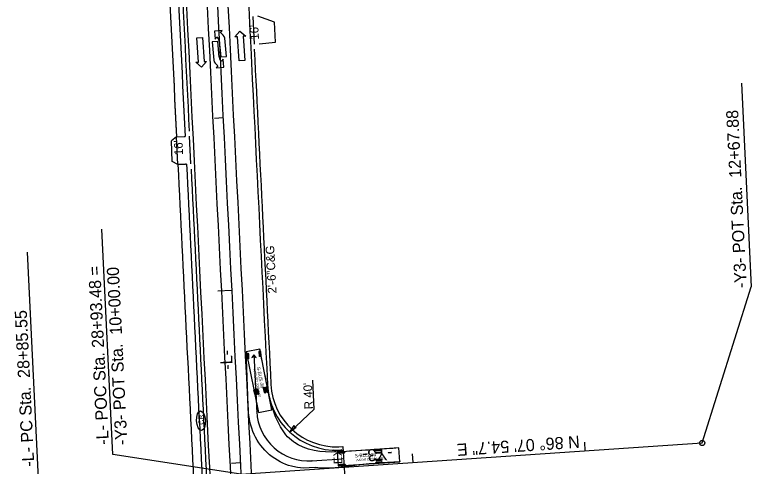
# Model space of a CAD drawing. Extents: x 2367848 to 2369479, y 800728 to 808616.
# Drawn here: x 2368732.6 to 2369159.2, y 803226.7 to 803488.2 of the extents above; entities that cross this region are included whole.
import ezdxf

# ---------------------------------------------------------------- set-up
doc = ezdxf.new("R2010")
doc.units = 0
for name, color, linetype in [('Prop AutoTurn Projected Path', 7, 'Continuous'), ('Prop AutoTurn Simulation', 7, 'Continuous'), ('Prop Conc 2ft 6in Curb and Gutter', 7, 'Continuous'), ('Prop Conc 4in Sidewalk', 7, 'Continuous'), ('Prop Conc Drive Radius Type', 7, 'Continuous'), ('Prop Conc Driveway', 7, 'Continuous'), ('Prop Dimension', 7, 'Continuous'), ('Prop EOT', 7, 'Continuous'), ('Prop Horizontal Alignment', 7, 'Continuous'), ('Prop Horizontal Alignment Direction Label', 7, 'Continuous'), ('Prop Horizontal Alignment Station Label', 7, 'Continuous'), ('Prop Horizontal Alignment Tick Large', 7, 'Continuous'), ('Prop Horizontal Alignment Tick Small', 7, 'Continuous'), ('Prop Lane Arrow CELL', 7, 'Continuous'), ('Prop Lane Lines', 7, 'Continuous'), ('Prop Shade Light', 7, 'Continuous'), ('Prop Terminator CELL', 7, 'Continuous'), ('Prop WCC CELL', 7, 'Continuous'), ('Prop WCR CELL', 7, 'Continuous')]:
    doc.layers.add(name, color=color, linetype=linetype)

# ---------------------------------------------------------------- blocks, each defined once
blk = doc.blocks.new('CR')
at = {"layer": 'Prop WCC CELL'}
blk.add_ellipse((0.02, -0.02), major_axis=(5.61, 0), ratio=0.462467, dxfattribs=at)
blk.add_text('CR', height=3, dxfattribs=at).set_placement((-2.34, -1.5))

msp = doc.modelspace()

# ---------------------------------------------------------------- linework, layer by layer
at = {"layer": 'Prop AutoTurn Projected Path'}
msp.add_line((2368904.73, 803229.94), (2368922.15, 803231.12), dxfattribs=at)
for centre, radius, start, end in [((2677047.33, 818679.94), 308560.21, 182.8586672, 182.8647861), ((2368902.7, 803259.87), 30, 182.8648, 273.8681)]:
    msp.add_arc(centre, radius, start, end, dxfattribs=at)
at = {"layer": 'Prop AutoTurn Simulation'}
for p, q in [((2368874.53, 803294.52), (2368866.68, 803292.95)), ((2368866.68, 803292.95), (2368873.73, 803257.85)), ((2368866.68, 803292.95), (2368866.68, 803292.95)), ((2368867.28, 803292.29), (2368867.45, 803288.97)), ((2368867.49, 803292.3), (2368867.66, 803288.98)), ((2368867.69, 803292.32), (2368867.87, 803288.99)), ((2368874.33, 803293.58), (2368874.49, 803290.25)), ((2368881.57, 803259.42), (2368874.53, 803294.52)), ((2368874.54, 803293.59), (2368874.69, 803290.26)), ((2368874.75, 803293.6), (2368874.9, 803290.27)), ((2368871.24, 803271.29), (2368871.9, 803268.02)), ((2368871.44, 803271.33), (2368872.1, 803268.06)), ((2368871.65, 803271.37), (2368872.3, 803268.1)), ((2368872.71, 803271.59), (2368873.37, 803268.32)), ((2368872.92, 803271.63), (2368873.57, 803268.36)), ((2368873.12, 803271.67), (2368873.78, 803268.4)), ((2368876.8, 803272.4), (2368877.45, 803269.14)), ((2368877, 803272.45), (2368877.66, 803269.18)), ((2368877.2, 803272.49), (2368877.86, 803269.22)), ((2368878.27, 803272.7), (2368878.92, 803269.43)), ((2368878.47, 803272.74), (2368879.13, 803269.47)), ((2368878.68, 803272.78), (2368879.33, 803269.51)), ((2368873.73, 803257.85), (2368881.57, 803259.42)), ((2368955.11, 803237.36), (2368919.39, 803234.94)), ((2368955.65, 803229.38), (2368955.11, 803237.36)), ((2368919.39, 803234.94), (2368919.93, 803226.96)), ((2368920.23, 803234.79), (2368923.56, 803235.02)), ((2368920.25, 803234.58), (2368923.57, 803234.81)), ((2368920.26, 803234.38), (2368923.59, 803234.6)), ((2368941.49, 803236.23), (2368944.81, 803236.45)), ((2368941.5, 803236.02), (2368944.83, 803236.24)), ((2368941.51, 803235.81), (2368944.84, 803236.04)), ((2368941.59, 803234.73), (2368944.91, 803234.96)), ((2368941.6, 803234.52), (2368944.93, 803234.75)), ((2368941.62, 803234.32), (2368944.94, 803234.54)), ((2368919.93, 803226.96), (2368955.65, 803229.38)), ((2368941.87, 803230.57), (2368945.19, 803230.8)), ((2368941.88, 803230.37), (2368945.21, 803230.59)), ((2368941.9, 803230.16), (2368945.22, 803230.38)), ((2368941.97, 803229.08), (2368945.3, 803229.3)), ((2368941.98, 803228.87), (2368945.31, 803229.09)), ((2368942, 803228.66), (2368945.32, 803228.89)), ((2368919.93, 803226.96), (2368919.93, 803226.96)), ((2368920.72, 803227.64), (2368924.04, 803227.87)), ((2368920.73, 803227.43), (2368924.06, 803227.66)), ((2368920.75, 803227.22), (2368924.07, 803227.45))]:
    msp.add_line(p, q, dxfattribs=at)
for points in [[(2368893.62, 803226.58), (2368892.94, 803226.75), (2368891.24, 803227.26), (2368889.56, 803227.86), (2368887.91, 803228.56), (2368886.28, 803229.36), (2368884.7, 803230.25), (2368883.16, 803231.22), (2368881.66, 803232.29), (2368880.22, 803233.44), (2368878.84, 803234.67), (2368877.53, 803235.97), (2368876.28, 803237.36), (2368875.11, 803238.81), (2368874.01, 803240.32), (2368873, 803241.9), (2368872.07, 803243.54), (2368871.23, 803245.22), (2368870.48, 803246.96), (2368869.83, 803248.73), (2368869.28, 803250.54), (2368868.82, 803252.38), (2368868.46, 803254.24), (2368868.21, 803256.13), (2368868.06, 803258.03), (2368867.95, 803259.92), (2368867.85, 803261.81), (2368867.76, 803263.68), (2368867.67, 803265.53), (2368867.59, 803267.38), (2368867.52, 803269.21), (2368867.45, 803271.04), (2368867.39, 803272.85), (2368867.32, 803274.65), (2368867.26, 803276.44), (2368867.2, 803278.23), (2368867.14, 803280.01), (2368867.08, 803281.77), (2368867.02, 803283.54), (2368866.96, 803285.29), (2368866.9, 803287.04), (2368866.83, 803288.78), (2368866.77, 803290.52), (2368866.71, 803292.26), (2368866.68, 803292.95)], [(2368894.57, 803240.55), (2368894.07, 803240.91), (2368892.85, 803241.83), (2368891.71, 803242.82), (2368890.65, 803243.85), (2368889.68, 803244.92), (2368888.78, 803246.04), (2368887.96, 803247.17), (2368887.21, 803248.33), (2368886.51, 803249.5), (2368885.86, 803250.67), (2368885.26, 803251.84), (2368884.7, 803253.02), (2368884.18, 803254.19), (2368883.7, 803255.36), (2368883.24, 803256.52), (2368882.82, 803257.68), (2368882.42, 803258.83), (2368882.04, 803259.97), (2368881.69, 803261.11), (2368881.35, 803262.24), (2368881.04, 803263.36), (2368880.74, 803264.48), (2368880.46, 803265.59), (2368880.19, 803266.7), (2368879.92, 803267.84), (2368879.65, 803269.04), (2368879.39, 803270.29), (2368879.13, 803271.59), (2368878.86, 803272.92), (2368878.59, 803274.29), (2368878.3, 803275.69), (2368878.02, 803277.11), (2368877.73, 803278.56), (2368877.43, 803280.03), (2368877.13, 803281.52), (2368876.83, 803283.02), (2368876.53, 803284.54), (2368876.22, 803286.08), (2368875.91, 803287.62), (2368875.6, 803289.18), (2368875.28, 803290.74), (2368874.97, 803292.31), (2368874.65, 803293.89), (2368874.53, 803294.52)], [(2368955.11, 803237.36), (2368951.54, 803237.12), (2368947.96, 803236.87), (2368944.39, 803236.63), (2368940.82, 803236.39), (2368937.25, 803236.15), (2368933.68, 803235.91), (2368930.1, 803235.67), (2368926.53, 803235.43), (2368922.96, 803235.19), (2368919.39, 803235.01), (2368919.39, 803235.01), (2368919.39, 803235.01), (2368916.03, 803234.95), (2368912.67, 803235.04), (2368909.33, 803235.34), (2368906.01, 803235.88), (2368902.76, 803236.7), (2368899.63, 803237.82), (2368896.72, 803239.23), (2368894.57, 803240.55)], [(2368955.65, 803229.38), (2368952.08, 803229.13), (2368948.5, 803228.89), (2368944.93, 803228.65), (2368941.36, 803228.41), (2368937.79, 803228.17), (2368934.22, 803227.82), (2368930.66, 803227.34), (2368927.08, 803226.86), (2368923.48, 803226.35), (2368919.85, 803225.94), (2368919.85, 803225.94), (2368916.43, 803225.7), (2368913.03, 803225.62), (2368909.69, 803225.71), (2368906.52, 803226.05), (2368903.17, 803225.83), (2368899.8, 803225.73), (2368896.37, 803226.04), (2368893.62, 803226.58)]]:
    msp.add_lwpolyline(points, dxfattribs=at)
for points in [[(2368867.23, 803292.29), (2368867.75, 803292.32), (2368867.93, 803291.86), (2368868.05, 803289.46), (2368867.92, 803288.99), (2368867.4, 803288.96), (2368867.22, 803289.42), (2368867.09, 803291.82)], [(2368874.28, 803293.58), (2368874.8, 803293.6), (2368874.98, 803293.15), (2368875.09, 803290.75), (2368874.95, 803290.28), (2368874.43, 803290.25), (2368874.26, 803290.71), (2368874.14, 803293.11)], [(2368871.1, 803291.29), (2368869.96, 803289.64), (2368871.15, 803290.29), (2368872.39, 803289.76)], [(2368871.19, 803271.28), (2368871.7, 803271.38), (2368871.95, 803270.96), (2368872.42, 803268.6), (2368872.36, 803268.11), (2368871.85, 803268.01), (2368871.6, 803268.44), (2368871.13, 803270.79)], [(2368872.66, 803271.57), (2368873.17, 803271.68), (2368873.42, 803271.25), (2368873.89, 803268.9), (2368873.83, 803268.41), (2368873.32, 803268.31), (2368873.07, 803268.73), (2368872.6, 803271.09)], [(2368876.75, 803272.39), (2368877.26, 803272.5), (2368877.5, 803272.07), (2368877.97, 803269.72), (2368877.91, 803269.23), (2368877.4, 803269.13), (2368877.16, 803269.55), (2368876.68, 803271.91)], [(2368878.22, 803272.69), (2368878.73, 803272.79), (2368878.97, 803272.37), (2368879.44, 803270.01), (2368879.38, 803269.52), (2368878.87, 803269.42), (2368878.63, 803269.85), (2368878.15, 803272.2)], [(2368941.52, 803235.76), (2368941.48, 803236.28), (2368941.94, 803236.47), (2368944.33, 803236.63), (2368944.81, 803236.5), (2368944.84, 803235.99), (2368944.39, 803235.8), (2368941.99, 803235.64)], [(2368920.27, 803234.32), (2368920.23, 803234.84), (2368920.69, 803235.03), (2368923.08, 803235.19), (2368923.56, 803235.07), (2368923.59, 803234.55), (2368923.14, 803234.36), (2368920.74, 803234.2)], [(2368941.62, 803234.26), (2368941.58, 803234.78), (2368942.04, 803234.97), (2368944.43, 803235.13), (2368944.91, 803235.01), (2368944.94, 803234.49), (2368944.49, 803234.3), (2368942.1, 803234.14)], [(2368920.75, 803227.17), (2368920.71, 803227.69), (2368921.17, 803227.88), (2368923.56, 803228.04), (2368924.04, 803227.92), (2368924.08, 803227.4), (2368923.62, 803227.21), (2368921.23, 803227.05)], [(2368941.9, 803230.11), (2368941.87, 803230.63), (2368942.32, 803230.81), (2368944.71, 803230.98), (2368945.19, 803230.85), (2368945.23, 803230.33), (2368944.77, 803230.14), (2368942.38, 803229.98)], [(2368942, 803228.61), (2368941.97, 803229.13), (2368942.42, 803229.32), (2368944.82, 803229.48), (2368945.29, 803229.35), (2368945.33, 803228.84), (2368944.87, 803228.65), (2368942.48, 803228.49)]]:
    msp.add_lwpolyline(points, close=True, dxfattribs=at)
for centre in [(2368866.68, 803292.95), (2368874.53, 803294.52), (2368871.1, 803291.29), (2368872.74, 803258.37), (2368872.74, 803258.37), (2368894.57, 803240.55), (2368894.57, 803240.55), (2368955.11, 803237.36), (2368904.73, 803229.94), (2368904.73, 803229.94), (2368922.15, 803231.12), (2368955.65, 803229.38)]:
    msp.add_circle(centre, 0.0417, dxfattribs=at)
at = {"layer": 'Prop Conc 2ft 6in Curb and Gutter'}
msp.add_line((2368920.35, 803238.03), (2368922.6, 803238.12), dxfattribs=at)
for centre, radius, start, end in [((2677047.33, 818679.94), 308591.21, 182.8136302, 182.8343013), ((2677047.33, 818679.94), 308551.21, 182.8258548, 182.8619441), ((2677047.33, 818679.94), 308591.21, 182.838386, 182.8728926), ((2368918.92, 803276.01), 38, 182.8619, 272.1661)]:
    msp.add_arc(centre, radius, start, end, dxfattribs=at)
at = {"layer": 'Prop Conc 4in Sidewalk'}
for centre, radius, start, end in [((2677047.33, 818679.94), 308598.71, 182.8130734, 182.834865), ((2677047.33, 818679.94), 308593.71, 182.8130812, 182.8348501), ((2368830.61, 803420.66), 3, 272.873, 282.6698), ((2677047.33, 818679.94), 308598.71, 182.8378289, 182.8728926), ((2368831.69, 803398.66), 3.02, 82.8674, 92.5967), ((2677047.33, 818679.94), 308593.71, 182.8378374, 182.8728926)]:
    msp.add_arc(centre, radius, start, end, dxfattribs=at)
at = {"layer": 'Prop Conc Drive Radius Type'}
for p, q in [((2368870.39, 803487.2), (2368871.17, 803471.22)), ((2368834.55, 803401.83), (2368833.75, 803417.81))]:
    msp.add_line(p, q, dxfattribs=at)
at = {"layer": 'Prop Conc Driveway'}
for p, q in [((2368826.26, 803417.44), (2368823.31, 803415.23)), ((2368826.26, 803417.44), (2368830.76, 803417.67)), ((2368827.06, 803401.46), (2368826.26, 803417.44)), ((2368823.79, 803403.25), (2368823.31, 803415.23)), ((2368827.06, 803401.46), (2368823.79, 803403.25)), ((2368827.06, 803401.46), (2368831.55, 803401.69))]:
    msp.add_line(p, q, dxfattribs=at)
at = {"layer": 'Prop Dimension'}
for p, q in [((2368906.01, 803259.71), (2368905.19, 803276.69)), ((2368891.9, 803246.51), (2368906.01, 803259.71))]:
    msp.add_line(p, q, dxfattribs=at)
at = {"layer": 'Prop EOT'}
for p, q in [((2368882.96, 803483.91), (2368873.38, 803487.34)), ((2368883.63, 803472.26), (2368882.96, 803483.91)), ((2368874.17, 803471.36), (2368883.63, 803472.26)), ((2368922.6, 803238.12), (2368924.32, 803212.65)), ((2368920.43, 803236.04), (2368922.73, 803236.12))]:
    msp.add_line(p, q, dxfattribs=at)
for centre, radius, start, end in [((2677047.33, 818679.94), 308589.21, 182.7974457, 182.8728926), ((2677047.33, 818679.94), 308553.21, 182.806587, 182.8619441), ((2368918.92, 803276.01), 40, 182.8619, 272.1661)]:
    msp.add_arc(centre, radius, start, end, dxfattribs=at)
at = {"layer": 'Prop Horizontal Alignment'}
msp.add_line((2368863.54, 803222.15), (2369130.81, 803240.22), dxfattribs=at)
msp.add_arc((2677047.33, 818679.94), 308571.21, 182.7974457, 182.8728926, dxfattribs=at)
at = {"layer": 'Prop Horizontal Alignment Station Label'}
for p, q in [((2369153.47, 803448.5), (2369159.22, 803330.64)), ((2368789.38, 803233.5), (2368783.01, 803364.06)), ((2368746.26, 803219.71), (2368739.87, 803350.68)), ((2369130.81, 803240.22), (2369159.22, 803330.64)), ((2368863.54, 803222.15), (2368789.38, 803233.5))]:
    msp.add_line(p, q, dxfattribs=at)
msp.add_circle((2369130.81, 803240.22), 1.5, dxfattribs=at)
at = {"layer": 'Prop Horizontal Alignment Tick Large'}
msp.add_line((2368858.22, 803328.53), (2368850.23, 803328.13), dxfattribs=at)
msp.add_line((2368858.22, 803328.53), (2368850.23, 803328.13), dxfattribs=at)
at = {"layer": 'Prop Horizontal Alignment Tick Small'}
for p, q in [((2368853.27, 803428.41), (2368848.27, 803428.16)), ((2368853.27, 803428.41), (2368848.27, 803428.16)), ((2369063.09, 803235.64), (2369062.75, 803240.63)), ((2368963.31, 803228.89), (2368962.98, 803233.88)), ((2368863.22, 803228.66), (2368858.22, 803228.41)), ((2368863.22, 803228.66), (2368858.22, 803228.41))]:
    msp.add_line(p, q, dxfattribs=at)
at = {"layer": 'Prop Lane Arrow CELL'}
for p, q in [((2368852.73, 803479), (2368848.3, 803478.59)), ((2368848.3, 803478.59), (2368848.71, 803474.11)), ((2368851.79, 803477.8), (2368852.73, 803479)), ((2368860.12, 803475.39), (2368863.01, 803478.73)), ((2368863.01, 803478.73), (2368866.4, 803475.8)), ((2368866.4, 803475.8), (2368864.91, 803475.7)), ((2368864.91, 803475.7), (2368865.82, 803461.73)), ((2368838.01, 803474.79), (2368841.3, 803475)), ((2368838.92, 803460.82), (2368838.01, 803474.79)), ((2368841.3, 803475), (2368842.21, 803461.03)), ((2368850.14, 803472.73), (2368846.86, 803472.43)), ((2368846.86, 803472.43), (2368847.83, 803461.92)), ((2368848.71, 803474.11), (2368849.66, 803475.25)), ((2368850.98, 803463.62), (2368850.14, 803472.73)), ((2368851.04, 803472.87), (2368851.88, 803463.75)), ((2368855.16, 803464.06), (2368854.19, 803474.56)), ((2368861.61, 803475.48), (2368860.12, 803475.39)), ((2368862.52, 803461.51), (2368861.61, 803475.48)), ((2368851.88, 803463.75), (2368855.16, 803464.06)), ((2368837.43, 803460.72), (2368838.92, 803460.82)), ((2368840.82, 803457.79), (2368837.43, 803460.72)), ((2368843.71, 803461.13), (2368840.82, 803457.79)), ((2368842.21, 803461.03), (2368843.71, 803461.13)), ((2368850.23, 803458.68), (2368849.28, 803457.54)), ((2368853.31, 803462.38), (2368852.36, 803461.24)), ((2368853.67, 803457.89), (2368853.31, 803462.38)), ((2368865.82, 803461.73), (2368862.52, 803461.51)), ((2368849.28, 803457.54), (2368853.67, 803457.89))]:
    msp.add_line(p, q, dxfattribs=at)
for centre, radius, start, end in [((2368849.08, 803473.31), 5.25, 13.9351, 59.2468), ((2368847.76, 803472.59), 3.27, 5.259, 54.9172), ((2368854.23, 803463.91), 3.27, 185.259, 234.9172), ((2368852.91, 803463.19), 5.25, 193.9351, 239.2468)]:
    msp.add_arc(centre, radius, start, end, dxfattribs=at)
at = {"layer": 'Prop Lane Lines'}
for radius in [308577.21, 308565.21]:
    msp.add_arc((2677047.33, 818679.94), radius, 182.7974457, 182.8728926, dxfattribs=at)
at = {"layer": 'Prop Shade Light'}
for p, q in [((2368826.27, 803417.44), (2368830.76, 803417.67)), ((2368831.55, 803401.69), (2368827.07, 803401.46))]:
    msp.add_line(p, q, dxfattribs=at)
for centre, radius, start, end in [((2677047.33, 818679.94), 308598.71, 182.8130734, 182.8348583), ((2677047.33, 818679.94), 308593.71, 182.8130812, 182.8348501), ((2368830.61, 803420.66), 3, 272.873, 282.6698), ((2677047.33, 818679.94), 308598.71, 182.8378289, 182.8728926), ((2368831.69, 803398.66), 3.02, 82.8674, 92.5967), ((2677047.33, 818679.94), 308593.71, 182.8378374, 182.8728926)]:
    msp.add_arc(centre, radius, start, end, dxfattribs=at)
at = {"layer": 'Prop Terminator CELL'}
msp.add_lwpolyline([(2368895.6, 803249.19), (2368891.9, 803246.51), (2368894.49, 803250.3), (2368894.66, 803249.33)], close=True, dxfattribs=at)

# ---------------------------------------------------------------- block references
at = {"layer": 'Prop WCR CELL', "rotation": 92.86625998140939}
msp.add_blockref('CR', (2368840.44, 803253.12), dxfattribs=at)

# ---------------------------------------------------------------- texts
at = {"layer": 'Prop AutoTurn Simulation'}
for s, height, rotation, p in [('S-BUS-36', 2, 281.3464, (2368872.71, 803284.06)), ('AASHTO 2001 (US)', 1.3333, 281.3464, (2368870.74, 803282.87)), ('(c) 2014 Transoft Solutions, Inc. All rights reserved.', 0.08, 281.3464, (2368873.77, 803277.78)), ('S-BUS-36', 2, 3.8681, (2368929.53, 803231.78)), ('AASHTO 2001 (US)', 1.3333, 3.8681, (2368930.46, 803229.67)), ('(c) 2014 Transoft Solutions, Inc. All rights reserved.', 0.08, 3.8681, (2368935.89, 803232.01))]:
    msp.add_text(s, height=height, rotation=rotation, dxfattribs=at).set_placement(p)
at = {"layer": 'Prop Dimension'}
for s, rotation, p in [("16'", 92.8248, (2368874.05, 803473.79)), ("16'", 92.8368, (2368830.11, 803406.98)), ('2\'-6"C&G', 92.9405, (2368884.23, 803326.94)), ("R 40'", 92.7929, (2368905.41, 803259.86)), ('EX', 92.7929, (2368922.4, 803228.14))]:
    msp.add_text(s, height=5, rotation=rotation, dxfattribs=at).set_placement(p)
at = {"layer": 'Prop Horizontal Alignment Direction Label'}
msp.add_text('N 86%%d 07\' 54.7" E', height=7, rotation=183.8681, dxfattribs=at).set_placement((2369059.6, 803244.47))
at = {"layer": 'Prop Horizontal Alignment Station Label'}
for s, rotation, p in [('-Y3- POT Sta.  12+67.88', 92.7928, (2369156.62, 803330.06)), ('-L- POC Sta. 28+93.48 =', 92.7929, (2368787.1, 803239.38)), ('-Y3- POT Sta.  10+00.00', 92.7929, (2368797.86, 803239.17)), ('-L- PC Sta.  28+85.55', 92.7929, (2368743.93, 803226.6)), ('-L-', 92.8585, (2368858.9, 803282.73)), ('-Y3-', 183.8681, (2368951.21, 803237.46))]:
    msp.add_text(s, height=7, rotation=rotation, dxfattribs=at).set_placement(p)

doc.saveas('drawing.dxf')
